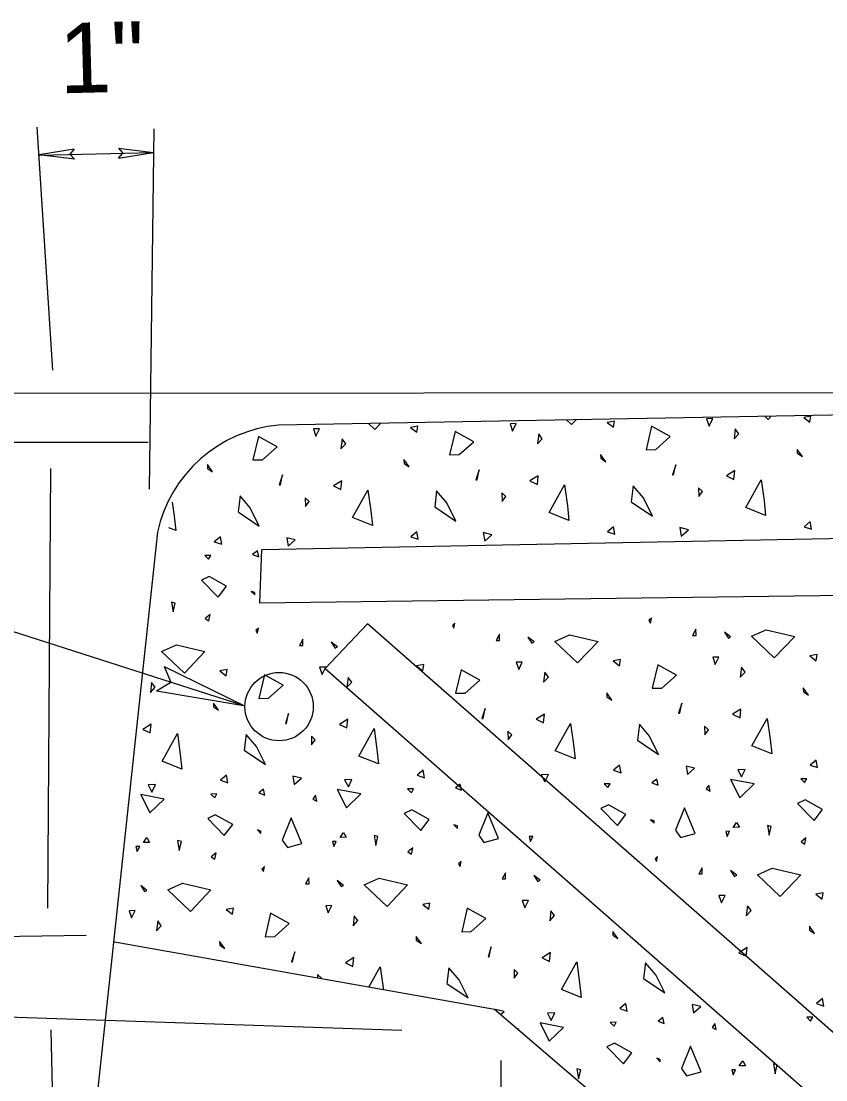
# Model space of a CAD drawing. Extents: x 1.75 to 8.12, y 0.37 to 10.28.
# Drawn here: x 3.66 to 4.349, y 4.294 to 5.199 of the extents above; entities that cross this region are included whole.
import ezdxf

# ---------------------------------------------------------------- set-up
doc = ezdxf.new("R2010")
doc.units = 0
for name, color, linetype in [('DETL-DIMS', 7, 'Continuous'), ('DETL-LINE', 7, 'Continuous'), ('DETL-NOTE', 7, 'Continuous'), ('DETL-PATT', 7, 'Continuous')]:
    doc.layers.add(name, color=color, linetype=linetype)

msp = doc.modelspace()

# ---------------------------------------------------------------- linework, layer by layer
at = {"layer": 'DETL-DIMS'}
for p, q in [((3.68746, 4.90095), (3.67414, 5.10872)), ((3.77008, 4.799), (3.77418, 5.10728)), ((3.70575, 5.08991), (3.67584, 5.08488)), ((3.70575, 5.08991), (3.70209, 5.08544)), ((3.74353, 5.09078), (3.77359, 5.08709)), ((3.74353, 5.09078), (3.74737, 5.08647)), ((3.70594, 5.08116), (3.67584, 5.08488)), ((3.67586, 5.08484), (3.77361, 5.08708)), ((3.70594, 5.08116), (3.70209, 5.08544)), ((3.74372, 5.08203), (3.77359, 5.08709)), ((3.74372, 5.08203), (3.74737, 5.08647)), ((4.81202, 4.88173), (2.71993, 4.88016)), ((3.76905, 4.839), (2.989, 4.83903)), ((3.68325, 4.44058), (3.68561, 4.81685)), ((3.78278, 4.64738), (3.85084, 4.61406)), ((3.78278, 4.64738), (3.78834, 4.63409)), ((3.77606, 4.62656), (3.78834, 4.63409)), ((3.77606, 4.62656), (3.85084, 4.61406)), ((3.71585, 4.4174), (3.24403, 4.40931)), ((3.24925, 4.36142), (3.98594, 4.33627)), ((3.69309, 4.05661), (3.68592, 4.33659)), ((4.07061, 4.31042), (4.0703, 4.01024))]:
    msp.add_line(p, q, dxfattribs=at)
msp.add_lwpolyline([(2.65657, 5.03824), (3.42138, 4.75178), (3.85084, 4.61404)], dxfattribs=at)
at = {"layer": 'DETL-LINE'}
for points in [[(3.77692, 4.76228), (3.69367, 3.98625), (3.69909, 3.21536), (5.42943, 3.21669), (5.4097, 4.8815), (3.88058, 4.85379)], [(4.51269, 3.21598), (4.5105, 3.97278), (4.06527, 4.35405), (3.74007, 4.41165)]]:
    msp.add_lwpolyline(points, dxfattribs=at)
for points in [[(3.86611, 4.74737), (5.26346, 4.77457), (5.28395, 4.75789), (5.29569, 4.74673), (5.29613, 4.72954), (5.30838, 3.58048), (5.24224, 3.59025), (5.23623, 4.71941), (3.86442, 4.70146)], [(3.92029, 4.64557), (5.1805, 3.53994), (5.21677, 3.57813), (3.95655, 4.68376)]]:
    msp.add_lwpolyline(points, close=True, dxfattribs=at)
msp.add_circle((3.88101, 4.61303), 0.02922, dxfattribs=at)
msp.add_arc((3.89135, 4.73712), 0.11717, 95.27779, 167.60068, dxfattribs=at)
at = {"layer": 'DETL-PATT'}
for points in [[(3.96806, 4.85539), (3.96292, 4.84998), (3.95744, 4.8552)], [(4.13503, 4.85841), (4.13112, 4.85429), (4.12694, 4.85827)], [(4.30201, 4.86144), (4.29931, 4.8586), (4.29643, 4.86134)], [(3.78963, 4.78793), (3.79126, 4.77606), (3.79258, 4.76359), (3.78674, 4.76595)], [(3.91694, 4.38033), (3.91718, 4.38066), (3.91385, 4.38382), (3.91392, 4.38087)], [(3.95778, 4.3731), (3.96745, 4.39045), (3.96991, 4.37251), (3.97007, 4.37092)], [(4.07053, 4.34956), (4.07346, 4.35215), (4.06616, 4.35396), (4.06629, 4.3532)], [(4.08586, 4.33644), (4.08558, 4.33771), (4.08515, 4.33704)]]:
    msp.add_lwpolyline(points, dxfattribs=at)
for points in [[(4.07859, 4.85495), (4.08074, 4.84875), (4.08383, 4.85508)], [(4.16158, 4.85607), (4.16694, 4.85196), (4.16781, 4.85723)], [(4.24678, 4.85926), (4.24894, 4.85306), (4.25203, 4.85939)], [(4.32978, 4.86038), (4.33514, 4.85627), (4.336, 4.86154)], [(3.91039, 4.85064), (3.91255, 4.84444), (3.91564, 4.85077)], [(3.99339, 4.85176), (3.99875, 4.84765), (3.99961, 4.85292)], [(4.035, 4.82857), (4.04747, 4.83965), (4.03149, 4.84849), (4.02675, 4.82836)], [(4.10306, 4.84632), (4.10203, 4.83779), (4.10617, 4.84215)], [(4.20319, 4.83288), (4.21566, 4.84395), (4.19968, 4.8528), (4.19494, 4.83267)], [(4.27126, 4.85063), (4.27023, 4.8421), (4.27437, 4.84646)], [(3.8668, 4.82426), (3.87927, 4.83534), (3.86329, 4.84418), (3.85855, 4.82405)], [(3.93487, 4.84201), (3.93384, 4.83348), (3.93798, 4.83784)], [(4.15603, 4.82867), (4.15612, 4.82542), (4.16044, 4.82253)], [(4.32423, 4.83298), (4.32431, 4.82973), (4.32864, 4.82684)], [(3.81964, 4.82005), (3.81973, 4.81681), (3.82405, 4.81391)], [(3.98784, 4.82436), (3.98792, 4.82111), (3.99225, 4.81822)], [(4.2175, 4.81124), (4.2185, 4.81127), (4.22028, 4.81981)], [(3.88111, 4.80262), (3.88211, 4.80265), (3.88389, 4.8112)], [(4.04931, 4.80693), (4.05031, 4.80696), (4.05209, 4.81551)], [(4.09559, 4.80612), (4.10192, 4.80303), (4.10273, 4.81055)], [(4.26379, 4.81043), (4.27012, 4.80734), (4.27093, 4.81486)], [(3.9274, 4.80181), (3.93373, 4.79872), (3.93454, 4.80624)], [(4.12765, 4.78468), (4.12897, 4.77221), (4.11204, 4.77903), (4.12519, 4.80262)], [(4.18398, 4.80188), (4.18233, 4.78833), (4.2004, 4.77604), (4.19275, 4.7916)], [(4.23979, 4.80031), (4.23998, 4.79281), (4.24312, 4.79714)], [(4.29585, 4.78899), (4.29717, 4.77652), (4.28024, 4.78334), (4.29339, 4.80693)], [(3.84759, 4.79326), (3.84594, 4.77971), (3.86401, 4.76742), (3.85636, 4.78298)], [(3.9034, 4.79169), (3.90359, 4.78419), (3.90673, 4.78852)], [(3.95946, 4.78037), (3.96078, 4.7679), (3.94385, 4.77472), (3.957, 4.79831)], [(4.01578, 4.79757), (4.01413, 4.78402), (4.0322, 4.77173), (4.02455, 4.78729)], [(4.07159, 4.796), (4.07178, 4.7885), (4.07493, 4.79283)], [(4.16712, 4.76694), (4.16198, 4.76255), (4.16828, 4.76046)], [(4.22391, 4.76614), (4.22509, 4.75892), (4.23121, 4.76433)], [(4.33531, 4.77124), (4.33017, 4.76686), (4.33648, 4.76477)], [(3.83073, 4.75832), (3.82559, 4.75393), (3.8319, 4.75185)], [(3.88752, 4.75752), (3.8887, 4.7503), (3.89482, 4.75571)], [(3.99892, 4.76263), (3.99378, 4.75824), (4.00009, 4.75615)], [(4.05571, 4.76183), (4.0569, 4.75461), (4.06301, 4.76002)], [(3.85837, 4.74327), (3.86368, 4.74116), (3.86255, 4.74638)], [(3.81739, 4.74222), (3.82072, 4.73906), (3.82264, 4.74236)], [(3.81468, 4.72114), (3.8288, 4.70675), (3.83606, 4.71619), (3.8211, 4.72431)], [(3.86021, 4.71056), (3.85719, 4.71148), (3.86026, 4.70856)], [(3.7889, 4.70248), (3.79036, 4.69401), (3.79217, 4.70156)], [(3.81776, 4.68846), (3.82081, 4.68654), (3.82193, 4.69182)], [(4.03144, 4.68443), (4.02924, 4.68238), (4.03055, 4.68016)], [(4.19963, 4.68874), (4.19743, 4.68669), (4.19874, 4.68447)], [(3.86324, 4.68012), (3.86104, 4.67807), (3.86235, 4.67585)], [(4.06944, 4.6749), (4.06658, 4.66958), (4.06958, 4.66966)], [(4.09715, 4.66736), (4.09912, 4.66841), (4.09376, 4.67253)], [(4.12948, 4.67444), (4.15388, 4.66881), (4.13634, 4.65036), (4.11686, 4.66887)], [(4.23764, 4.67921), (4.23477, 4.67389), (4.23777, 4.67396)], [(4.26534, 4.67167), (4.26731, 4.67272), (4.26196, 4.67684)], [(4.29767, 4.67875), (4.32207, 4.67312), (4.30454, 4.65467), (4.28506, 4.67318)], [(3.79309, 4.66582), (3.81749, 4.6602), (3.79995, 4.64174), (3.78047, 4.66025)], [(3.90125, 4.6706), (3.89838, 4.66527), (3.90138, 4.66535)], [(3.92895, 4.66305), (3.93092, 4.6641), (3.92557, 4.66822)], [(4.252, 4.65532), (4.25416, 4.64913), (4.25725, 4.65546)], [(4.335, 4.65645), (4.34036, 4.65234), (4.34123, 4.65761)], [(3.91562, 4.64671), (3.91777, 4.64051), (3.92086, 4.64684)], [(3.99861, 4.64783), (4.00397, 4.64372), (4.00484, 4.64899)], [(4.08381, 4.65101), (4.08597, 4.64482), (4.08906, 4.65115)], [(4.16681, 4.65214), (4.17217, 4.64803), (4.17303, 4.6533)], [(4.20842, 4.62895), (4.22089, 4.64002), (4.2049, 4.64886), (4.20017, 4.62874)], [(4.27648, 4.6467), (4.27545, 4.63817), (4.27959, 4.64253)], [(3.83042, 4.64352), (3.83578, 4.63941), (3.83664, 4.64468)], [(3.87203, 4.62033), (3.8845, 4.6314), (3.86852, 4.64025), (3.86378, 4.62012)], [(3.94009, 4.63808), (3.93906, 4.62955), (3.9432, 4.63391)], [(4.04022, 4.62464), (4.05269, 4.63571), (4.03671, 4.64456), (4.03197, 4.62443)], [(4.10829, 4.64239), (4.10726, 4.63386), (4.1114, 4.63822)], [(3.7719, 4.63377), (3.77087, 4.62524), (3.77501, 4.6296)], [(4.32945, 4.62905), (4.32954, 4.6258), (4.33386, 4.62291)], [(4.16126, 4.62474), (4.16134, 4.62149), (4.16567, 4.6186)], [(3.82487, 4.61612), (3.82495, 4.61287), (3.82928, 4.60998)], [(4.05453, 4.603), (4.05553, 4.60302), (4.05731, 4.61157)], [(4.22273, 4.60731), (4.22372, 4.60733), (4.22551, 4.61588)], [(4.26901, 4.60649), (4.27534, 4.6034), (4.27615, 4.61093)], [(3.88634, 4.59869), (3.88734, 4.59872), (3.88912, 4.60726)], [(3.93262, 4.59787), (3.93895, 4.59479), (3.93976, 4.60231)], [(4.10082, 4.60218), (4.10715, 4.59909), (4.10796, 4.60662)], [(4.30107, 4.58506), (4.30239, 4.57259), (4.28546, 4.57941), (4.29861, 4.603)], [(3.76443, 4.59357), (3.77076, 4.59048), (3.77157, 4.598)], [(3.96468, 4.57644), (3.966, 4.56397), (3.94907, 4.57079), (3.96222, 4.59438)], [(4.07682, 4.59207), (4.07701, 4.58457), (4.08015, 4.5889)], [(4.13288, 4.58075), (4.1342, 4.56828), (4.11727, 4.5751), (4.13042, 4.59869)], [(4.1892, 4.59795), (4.18755, 4.5844), (4.20562, 4.57211), (4.19797, 4.58767)], [(4.24501, 4.59637), (4.2452, 4.58888), (4.24834, 4.59321)], [(3.79649, 4.57213), (3.79781, 4.55966), (3.78088, 4.56648), (3.79403, 4.59007)], [(3.85281, 4.58933), (3.85116, 4.57578), (3.86923, 4.56349), (3.86158, 4.57905)], [(3.90862, 4.58776), (3.90881, 4.58026), (3.91195, 4.58459)], [(4.34054, 4.56731), (4.3354, 4.56293), (4.3417, 4.56084)], [(4.00415, 4.55869), (3.99901, 4.55431), (4.00531, 4.55222)], [(4.10528, 4.55478), (4.10844, 4.54861), (4.11153, 4.55494)], [(4.17234, 4.563), (4.1672, 4.55862), (4.17351, 4.55653)], [(4.22913, 4.56221), (4.23032, 4.55498), (4.23643, 4.56039)], [(4.27348, 4.55909), (4.27664, 4.55292), (4.27972, 4.55925)], [(3.76889, 4.54616), (3.77205, 4.53999), (3.77514, 4.54632)], [(3.83595, 4.55438), (3.83081, 4.55), (3.83712, 4.54791)], [(3.89274, 4.55359), (3.89393, 4.54637), (3.90004, 4.55178)], [(3.93709, 4.55047), (3.94025, 4.5443), (3.94333, 4.55063)], [(4.03179, 4.54365), (4.0371, 4.54153), (4.03596, 4.54675)], [(4.159, 4.54691), (4.16233, 4.54374), (4.16425, 4.54704)], [(4.19999, 4.54796), (4.20529, 4.54584), (4.20416, 4.55106)], [(4.24639, 4.54264), (4.24969, 4.54073), (4.24855, 4.54595)], [(4.26719, 4.55068), (4.27509, 4.53513), (4.28729, 4.54694)], [(4.3272, 4.55121), (4.33053, 4.54805), (4.33244, 4.55135)], [(3.76261, 4.53775), (3.77051, 4.5222), (3.78271, 4.53401)], [(3.82261, 4.53829), (3.82594, 4.53512), (3.82786, 4.53842)], [(3.8636, 4.53934), (3.8689, 4.53722), (3.86777, 4.54245)], [(3.91, 4.53402), (3.9133, 4.53211), (3.91217, 4.53733)], [(3.9308, 4.54206), (3.9387, 4.52651), (3.9509, 4.53832)], [(3.99081, 4.5426), (3.99414, 4.53943), (3.99605, 4.54273)], [(4.15629, 4.52583), (4.17041, 4.51144), (4.17767, 4.52088), (4.16271, 4.52899)], [(4.32448, 4.53014), (4.33861, 4.51575), (4.34587, 4.52518), (4.33091, 4.5333)], [(3.8199, 4.51721), (3.83402, 4.50282), (3.84128, 4.51226), (3.82632, 4.52038)], [(3.9881, 4.52152), (4.00222, 4.50713), (4.00948, 4.51657), (3.99452, 4.52469)], [(4.05625, 4.49676), (4.06866, 4.50033), (4.0596, 4.5221), (4.05184, 4.50315)], [(4.22445, 4.50107), (4.23686, 4.50464), (4.2278, 4.52641), (4.22003, 4.50746)], [(3.88806, 4.49245), (3.90047, 4.49602), (3.89141, 4.51779), (3.88364, 4.49884)], [(4.03363, 4.51093), (4.03061, 4.51186), (4.03368, 4.50893)], [(4.20183, 4.51524), (4.1988, 4.51616), (4.20188, 4.51324)], [(4.27238, 4.51405), (4.27474, 4.50986), (4.26949, 4.50972)], [(4.2987, 4.51147), (4.30017, 4.50301), (4.30198, 4.51056)], [(3.7678, 4.50112), (3.77015, 4.49693), (3.76491, 4.4968)], [(3.86544, 4.50662), (3.86241, 4.50755), (3.86549, 4.50462)], [(3.93599, 4.50543), (3.93835, 4.50124), (3.9331, 4.50111)], [(3.96231, 4.50285), (3.96378, 4.49439), (3.96559, 4.50194)], [(4.09488, 4.502), (4.09599, 4.49778), (4.09813, 4.50208)], [(4.26307, 4.50631), (4.26418, 4.50208), (4.26632, 4.50639)], [(4.32757, 4.49746), (4.33062, 4.49553), (4.33174, 4.50081)], [(3.75849, 4.49338), (3.7596, 4.48916), (3.76174, 4.49346)], [(3.79412, 4.49854), (3.79559, 4.49008), (3.79739, 4.49763)], [(3.92669, 4.49769), (3.92779, 4.49347), (3.92993, 4.49777)], [(3.99118, 4.48884), (3.99423, 4.48692), (3.99535, 4.4922)], [(3.82299, 4.48453), (3.82604, 4.48261), (3.82715, 4.48789)], [(4.20486, 4.48481), (4.20266, 4.48275), (4.20397, 4.48054)], [(3.86847, 4.47619), (3.86627, 4.47413), (3.86758, 4.47192)], [(4.03666, 4.4805), (4.03446, 4.47844), (4.03577, 4.47623)], [(4.24286, 4.47528), (4.24, 4.46995), (4.243, 4.47003)], [(4.30289, 4.47482), (4.3273, 4.46919), (4.30976, 4.45074), (4.29028, 4.46924)], [(3.90647, 4.46666), (3.90361, 4.46134), (3.90661, 4.46141)], [(3.93418, 4.45912), (3.93615, 4.46017), (3.93079, 4.46428)], [(3.9665, 4.4662), (3.99091, 4.46057), (3.97337, 4.44212), (3.95389, 4.46062)], [(4.07467, 4.47097), (4.0718, 4.46565), (4.0748, 4.46572)], [(4.10237, 4.46343), (4.10434, 4.46448), (4.09899, 4.46859)], [(4.27057, 4.46774), (4.27254, 4.46879), (4.26718, 4.4729)], [(3.76598, 4.45481), (3.76795, 4.45586), (3.7626, 4.45997)], [(3.79831, 4.46189), (3.82271, 4.45626), (3.80518, 4.43781), (3.7857, 4.45632)], [(4.08903, 4.44708), (4.09119, 4.44088), (4.09428, 4.44722)], [(4.25723, 4.45139), (4.25939, 4.44519), (4.26248, 4.45152)], [(4.34023, 4.45252), (4.34559, 4.4484), (4.34645, 4.45368)], [(3.75265, 4.43846), (3.7548, 4.43227), (3.75789, 4.4386)], [(3.83564, 4.43959), (3.841, 4.43547), (3.84187, 4.44075)], [(3.92084, 4.44277), (3.923, 4.43658), (3.92609, 4.44291)], [(4.00384, 4.4439), (4.0092, 4.43978), (4.01006, 4.44506)], [(4.04545, 4.42071), (4.05792, 4.43178), (4.04193, 4.44062), (4.0372, 4.42049)], [(4.11351, 4.43846), (4.11248, 4.42993), (4.11662, 4.43428)], [(4.28171, 4.44276), (4.28068, 4.43423), (4.28482, 4.43859)], [(3.77712, 4.42984), (3.77609, 4.42131), (3.78023, 4.42567)], [(3.87725, 4.4164), (3.88972, 4.42747), (3.87374, 4.43631), (3.869, 4.41619)], [(3.94532, 4.43415), (3.94429, 4.42562), (3.94843, 4.42997)], [(4.16648, 4.42081), (4.16657, 4.41756), (4.17089, 4.41467)], [(4.33468, 4.42512), (4.33476, 4.42187), (4.33909, 4.41898)], [(3.83009, 4.41219), (3.83018, 4.40894), (3.8345, 4.40605)], [(3.99829, 4.4165), (3.99837, 4.41325), (4.0027, 4.41036)], [(3.89156, 4.39476), (3.89256, 4.39478), (3.89434, 4.40333)], [(4.05975, 4.39907), (4.06075, 4.39909), (4.06254, 4.40764)], [(4.10604, 4.39825), (4.11237, 4.39516), (4.11318, 4.40268)], [(4.27424, 4.40256), (4.28057, 4.39947), (4.28137, 4.40699)], [(3.93785, 4.39394), (3.94418, 4.39085), (3.94498, 4.39838)], [(4.1381, 4.37681), (4.13942, 4.36434), (4.12249, 4.37116), (4.13564, 4.39476)], [(4.19443, 4.39401), (4.19277, 4.38047), (4.21085, 4.36817), (4.20319, 4.38373)], [(4.02623, 4.3897), (4.02458, 4.37616), (4.04265, 4.36387), (4.035, 4.37942)], [(4.08204, 4.38813), (4.08223, 4.38064), (4.08537, 4.38497)], [(4.17757, 4.35907), (4.17243, 4.35469), (4.17873, 4.3526)], [(4.23436, 4.35827), (4.23554, 4.35105), (4.24166, 4.35646)], [(4.34576, 4.36338), (4.34062, 4.359), (4.34693, 4.35691)], [(4.11051, 4.35085), (4.11367, 4.34468), (4.11675, 4.35101)], [(4.20521, 4.34402), (4.21052, 4.34191), (4.20938, 4.34713)], [(4.33242, 4.34728), (4.33575, 4.34412), (4.33767, 4.34742)], [(4.10422, 4.34244), (4.11212, 4.32688), (4.12432, 4.3387)], [(4.16423, 4.34297), (4.16756, 4.33981), (4.16947, 4.34311)], [(4.25161, 4.33871), (4.25491, 4.33679), (4.25378, 4.34202)], [(4.16151, 4.3219), (4.17564, 4.3075), (4.1829, 4.31694), (4.16794, 4.32506)], [(4.22967, 4.29713), (4.24208, 4.3007), (4.23302, 4.32248), (4.22526, 4.30352)], [(4.20705, 4.31131), (4.20403, 4.31223), (4.2071, 4.30931)], [(4.13573, 4.30323), (4.1372, 4.29476), (4.13901, 4.30231)], [(4.2683, 4.30237), (4.26941, 4.29815), (4.27155, 4.30246)], [(4.2776, 4.31012), (4.27996, 4.30592), (4.27471, 4.30579)], [(4.30393, 4.30754), (4.3054, 4.29907), (4.3072, 4.30662)]]:
    msp.add_lwpolyline(points, close=True, dxfattribs=at)

# ---------------------------------------------------------------- texts
at = {"layer": 'DETL-NOTE'}
msp.add_text('1"', height=0.06, rotation=1.46756, dxfattribs=at).set_placement((3.69347, 5.13756))

doc.saveas('drawing.dxf')
